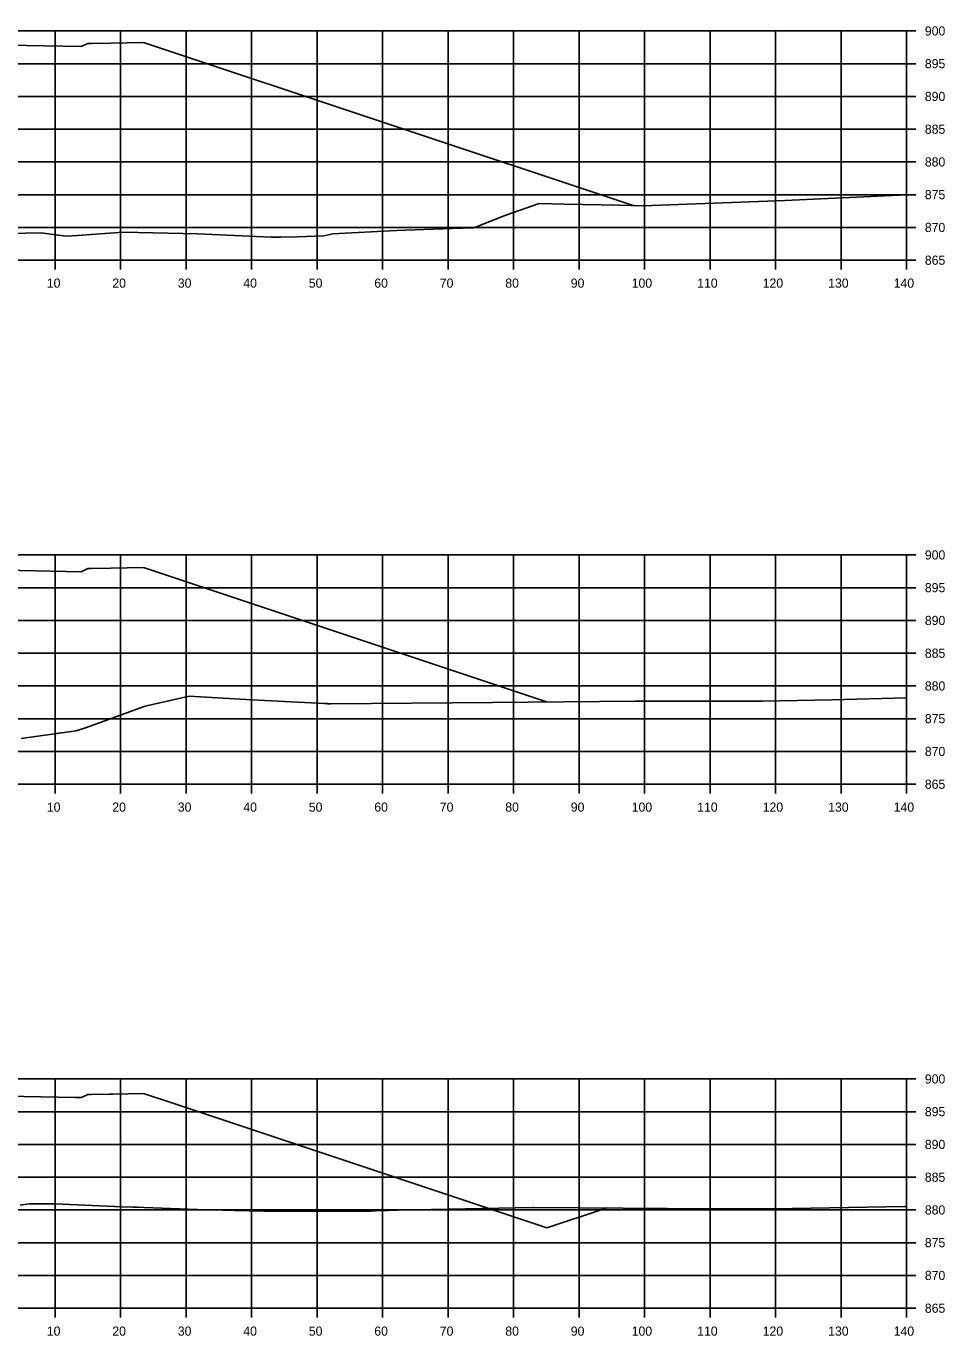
# Model space of a CAD drawing. Extents: x 1098669 to 1198896, y 698679 to 704410.
# Drawn here: x 1113504.5 to 1113644.7, y 702234.3 to 702434.3 of the extents above; entities that cross this region are included whole.
import ezdxf

# ---------------------------------------------------------------- set-up
doc = ezdxf.new("R2010")
doc.units = 0
for name, color, linetype in [('R_Alt Surface', 7, 'Continuous'), ('R_Axis', 7, 'Continuous'), ('R_Axis Annot', 7, 'Continuous'), ('R_Fin Surface', 7, 'Continuous'), ('R_Grid', 7, 'Continuous')]:
    doc.layers.add(name, color=color, linetype=linetype)

msp = doc.modelspace()

# ---------------------------------------------------------------- linework, layer by layer
at = {"layer": 'R_Alt Surface'}
for points in [[(1113497.26, 702402.53), (1113506.69, 702402.73), (1113510.18, 702402.26), (1113510.55, 702402.21), (1113512.3, 702402.34), (1113519.29, 702402.86), (1113530.68, 702402.6), (1113541.84, 702402.08), (1113543.32, 702402.09), (1113545.85, 702402.15), (1113549.89, 702402.27), (1113551.29, 702402.56), (1113561.02, 702403.07), (1113569.51, 702403.4), (1113572.81, 702403.52), (1113577.68, 702405.41), (1113582.79, 702407.2), (1113586.67, 702407.12), (1113595.04, 702406.94), (1113598.59, 702406.87), (1113620.33, 702407.68), (1113638.87, 702408.53)], [(1113503.69, 702325.53), (1113511.32, 702326.6), (1113512.08, 702326.7), (1113513.53, 702327.18), (1113522.61, 702330.47), (1113529.34, 702331.98), (1113537.15, 702331.52), (1113540.91, 702331.34), (1113549.98, 702330.87), (1113550.42, 702330.86), (1113550.45, 702330.85), (1113550.57, 702330.85), (1113550.98, 702330.85), (1113575.64, 702331.02), (1113597.43, 702331.26), (1113613.54, 702331.23), (1113616.89, 702331.21), (1113627.51, 702331.46), (1113638.87, 702331.76)], [(1113503.54, 702254.29), (1113504.92, 702254.48), (1113508.87, 702254.47), (1113519.04, 702254.05), (1113520.73, 702253.99), (1113521.43, 702253.96), (1113522.46, 702253.92), (1113530.58, 702253.61), (1113536.29, 702253.48), (1113540.7, 702253.36), (1113542.91, 702253.39), (1113557.08, 702253.38), (1113558.73, 702253.46), (1113559.71, 702253.46), (1113561.16, 702253.54), (1113581.75, 702253.92), (1113581.84, 702253.92), (1113581.91, 702253.92), (1113581.92, 702253.92), (1113581.99, 702253.92), (1113602.35, 702253.8), (1113611.61, 702253.75), (1113618.61, 702253.73), (1113638.57, 702254.1), (1113638.87, 702254.1)]]:
    msp.add_lwpolyline(points, dxfattribs=at)
at = {"layer": 'R_Axis'}
for p, q in [((1113638.87, 702398.56), (1113638.87, 702433.56)), ((1113640.27, 702433.56), (1113638.87, 702433.56)), ((1113640.27, 702428.56), (1113638.87, 702428.56)), ((1113640.27, 702423.56), (1113638.87, 702423.56)), ((1113640.27, 702418.56), (1113638.87, 702418.56)), ((1113640.27, 702413.56), (1113638.87, 702413.56)), ((1113640.27, 702408.56), (1113638.87, 702408.56)), ((1113640.27, 702403.56), (1113638.87, 702403.56)), ((1113358.87, 702398.56), (1113638.87, 702398.56)), ((1113508.87, 702397.16), (1113508.87, 702398.56)), ((1113518.87, 702397.16), (1113518.87, 702398.56)), ((1113528.87, 702397.16), (1113528.87, 702398.56)), ((1113538.87, 702397.16), (1113538.87, 702398.56)), ((1113548.87, 702397.16), (1113548.87, 702398.56)), ((1113558.87, 702397.16), (1113558.87, 702398.56)), ((1113568.87, 702397.16), (1113568.87, 702398.56)), ((1113578.87, 702397.16), (1113578.87, 702398.56)), ((1113588.87, 702397.16), (1113588.87, 702398.56)), ((1113598.87, 702397.16), (1113598.87, 702398.56)), ((1113608.87, 702397.16), (1113608.87, 702398.56)), ((1113618.87, 702397.16), (1113618.87, 702398.56)), ((1113628.87, 702397.16), (1113628.87, 702398.56)), ((1113638.87, 702397.16), (1113638.87, 702398.56)), ((1113640.27, 702398.56), (1113638.87, 702398.56)), ((1113638.87, 702318.56), (1113638.87, 702353.56)), ((1113640.27, 702353.56), (1113638.87, 702353.56)), ((1113640.27, 702348.56), (1113638.87, 702348.56)), ((1113640.27, 702343.56), (1113638.87, 702343.56)), ((1113640.27, 702338.56), (1113638.87, 702338.56)), ((1113640.27, 702333.56), (1113638.87, 702333.56)), ((1113640.27, 702328.56), (1113638.87, 702328.56)), ((1113640.27, 702323.56), (1113638.87, 702323.56)), ((1113358.87, 702318.56), (1113638.87, 702318.56)), ((1113508.87, 702317.16), (1113508.87, 702318.56)), ((1113518.87, 702317.16), (1113518.87, 702318.56)), ((1113528.87, 702317.16), (1113528.87, 702318.56)), ((1113538.87, 702317.16), (1113538.87, 702318.56)), ((1113548.87, 702317.16), (1113548.87, 702318.56)), ((1113558.87, 702317.16), (1113558.87, 702318.56)), ((1113568.87, 702317.16), (1113568.87, 702318.56)), ((1113578.87, 702317.16), (1113578.87, 702318.56)), ((1113588.87, 702317.16), (1113588.87, 702318.56)), ((1113598.87, 702317.16), (1113598.87, 702318.56)), ((1113608.87, 702317.16), (1113608.87, 702318.56)), ((1113618.87, 702317.16), (1113618.87, 702318.56)), ((1113628.87, 702317.16), (1113628.87, 702318.56)), ((1113638.87, 702317.16), (1113638.87, 702318.56)), ((1113640.27, 702318.56), (1113638.87, 702318.56)), ((1113638.87, 702238.56), (1113638.87, 702273.56)), ((1113640.27, 702273.56), (1113638.87, 702273.56)), ((1113640.27, 702268.56), (1113638.87, 702268.56)), ((1113640.27, 702263.56), (1113638.87, 702263.56)), ((1113640.27, 702258.56), (1113638.87, 702258.56)), ((1113640.27, 702253.56), (1113638.87, 702253.56)), ((1113640.27, 702248.56), (1113638.87, 702248.56)), ((1113640.27, 702243.56), (1113638.87, 702243.56)), ((1113358.87, 702238.56), (1113638.87, 702238.56)), ((1113508.87, 702237.16), (1113508.87, 702238.56)), ((1113518.87, 702237.16), (1113518.87, 702238.56)), ((1113528.87, 702237.16), (1113528.87, 702238.56)), ((1113538.87, 702237.16), (1113538.87, 702238.56)), ((1113548.87, 702237.16), (1113548.87, 702238.56)), ((1113558.87, 702237.16), (1113558.87, 702238.56)), ((1113568.87, 702237.16), (1113568.87, 702238.56)), ((1113578.87, 702237.16), (1113578.87, 702238.56)), ((1113588.87, 702237.16), (1113588.87, 702238.56)), ((1113598.87, 702237.16), (1113598.87, 702238.56)), ((1113608.87, 702237.16), (1113608.87, 702238.56)), ((1113618.87, 702237.16), (1113618.87, 702238.56)), ((1113628.87, 702237.16), (1113628.87, 702238.56)), ((1113638.87, 702237.16), (1113638.87, 702238.56)), ((1113640.27, 702238.56), (1113638.87, 702238.56))]:
    msp.add_line(p, q, dxfattribs=at)
at = {"layer": 'R_Fin Surface'}
for points in [[(1113444.85, 702421.64), (1113454.54, 702424.87), (1113458.59, 702426.22), (1113462.54, 702427.54), (1113475.37, 702431.81), (1113480.37, 702431.71), (1113483.37, 702431.65), (1113483.87, 702431.65), (1113484.87, 702431.17), (1113498.87, 702431.45), (1113512.87, 702431.17), (1113513.87, 702431.65), (1113514.37, 702431.65), (1113517.37, 702431.71), (1113522.37, 702431.81), (1113597.11, 702406.9)], [(1113408.45, 702329.33), (1113427.7, 702335.74), (1113432.99, 702337.5), (1113445.37, 702341.63), (1113455.37, 702344.96), (1113461.27, 702346.93), (1113475.37, 702351.63), (1113480.37, 702351.53), (1113483.37, 702351.47), (1113483.87, 702351.47), (1113484.87, 702350.99), (1113498.87, 702351.27), (1113512.87, 702350.99), (1113513.87, 702351.47), (1113514.37, 702351.47), (1113517.37, 702351.53), (1113522.37, 702351.63), (1113583.92, 702331.11)], [(1113498.87, 702270.99), (1113511.94, 702270.73), (1113512.87, 702270.71), (1113512.93, 702270.74), (1113513.87, 702271.19), (1113513.9, 702271.19), (1113514.37, 702271.19), (1113517.17, 702271.25), (1113517.37, 702271.25), (1113517.7, 702271.26), (1113522.37, 702271.35), (1113526.41, 702270), (1113583.97, 702250.82), (1113592.42, 702253.63), (1113593.09, 702253.86)]]:
    msp.add_lwpolyline(points, dxfattribs=at)
at = {"layer": 'R_Grid'}
for p, q in [((1113358.87, 702433.56), (1113638.87, 702433.56)), ((1113508.87, 702398.56), (1113508.87, 702433.56)), ((1113518.87, 702398.56), (1113518.87, 702433.56)), ((1113528.87, 702398.56), (1113528.87, 702433.56)), ((1113538.87, 702398.56), (1113538.87, 702433.56)), ((1113548.87, 702398.56), (1113548.87, 702433.56)), ((1113558.87, 702398.56), (1113558.87, 702433.56)), ((1113568.87, 702398.56), (1113568.87, 702433.56)), ((1113578.87, 702398.56), (1113578.87, 702433.56)), ((1113588.87, 702398.56), (1113588.87, 702433.56)), ((1113598.87, 702398.56), (1113598.87, 702433.56)), ((1113608.87, 702398.56), (1113608.87, 702433.56)), ((1113618.87, 702398.56), (1113618.87, 702433.56)), ((1113628.87, 702398.56), (1113628.87, 702433.56)), ((1113638.87, 702398.56), (1113638.87, 702433.56)), ((1113358.87, 702428.56), (1113638.87, 702428.56)), ((1113358.87, 702423.56), (1113638.87, 702423.56)), ((1113358.87, 702418.56), (1113638.87, 702418.56)), ((1113358.87, 702413.56), (1113638.87, 702413.56)), ((1113358.87, 702408.56), (1113638.87, 702408.56)), ((1113358.87, 702403.56), (1113638.87, 702403.56)), ((1113358.87, 702398.56), (1113638.87, 702398.56)), ((1113358.87, 702353.56), (1113638.87, 702353.56)), ((1113508.87, 702318.56), (1113508.87, 702353.56)), ((1113518.87, 702318.56), (1113518.87, 702353.56)), ((1113528.87, 702318.56), (1113528.87, 702353.56)), ((1113538.87, 702318.56), (1113538.87, 702353.56)), ((1113548.87, 702318.56), (1113548.87, 702353.56)), ((1113558.87, 702318.56), (1113558.87, 702353.56)), ((1113568.87, 702318.56), (1113568.87, 702353.56)), ((1113578.87, 702318.56), (1113578.87, 702353.56)), ((1113588.87, 702318.56), (1113588.87, 702353.56)), ((1113598.87, 702318.56), (1113598.87, 702353.56)), ((1113608.87, 702318.56), (1113608.87, 702353.56)), ((1113618.87, 702318.56), (1113618.87, 702353.56)), ((1113628.87, 702318.56), (1113628.87, 702353.56)), ((1113638.87, 702318.56), (1113638.87, 702353.56)), ((1113358.87, 702348.56), (1113638.87, 702348.56)), ((1113358.87, 702343.56), (1113638.87, 702343.56)), ((1113358.87, 702338.56), (1113638.87, 702338.56)), ((1113358.87, 702333.56), (1113638.87, 702333.56)), ((1113358.87, 702328.56), (1113638.87, 702328.56)), ((1113358.87, 702323.56), (1113638.87, 702323.56)), ((1113358.87, 702318.56), (1113638.87, 702318.56)), ((1113358.87, 702273.56), (1113638.87, 702273.56)), ((1113508.87, 702238.56), (1113508.87, 702273.56)), ((1113518.87, 702238.56), (1113518.87, 702273.56)), ((1113528.87, 702238.56), (1113528.87, 702273.56)), ((1113538.87, 702238.56), (1113538.87, 702273.56)), ((1113548.87, 702238.56), (1113548.87, 702273.56)), ((1113558.87, 702238.56), (1113558.87, 702273.56)), ((1113568.87, 702238.56), (1113568.87, 702273.56)), ((1113578.87, 702238.56), (1113578.87, 702273.56)), ((1113588.87, 702238.56), (1113588.87, 702273.56)), ((1113598.87, 702238.56), (1113598.87, 702273.56)), ((1113608.87, 702238.56), (1113608.87, 702273.56)), ((1113618.87, 702238.56), (1113618.87, 702273.56)), ((1113628.87, 702238.56), (1113628.87, 702273.56)), ((1113638.87, 702238.56), (1113638.87, 702273.56)), ((1113358.87, 702268.56), (1113638.87, 702268.56)), ((1113358.87, 702263.56), (1113638.87, 702263.56)), ((1113358.87, 702258.56), (1113638.87, 702258.56)), ((1113358.87, 702253.56), (1113638.87, 702253.56)), ((1113358.87, 702248.56), (1113638.87, 702248.56)), ((1113358.87, 702243.56), (1113638.87, 702243.56)), ((1113358.87, 702238.56), (1113638.87, 702238.56))]:
    msp.add_line(p, q, dxfattribs=at)

# ---------------------------------------------------------------- texts
at = {"layer": 'R_Axis Annot'}
for s, p in [('900', (1113641.67, 702432.86)), ('895', (1113641.67, 702427.86)), ('890', (1113641.67, 702422.86)), ('885', (1113641.67, 702417.86)), ('880', (1113641.67, 702412.86)), ('875', (1113641.67, 702407.86)), ('870', (1113641.67, 702402.86)), ('865', (1113641.67, 702397.86)), ('10', (1113507.61, 702394.36)), ('20', (1113517.61, 702394.36)), ('30', (1113527.61, 702394.36)), ('40', (1113537.61, 702394.36)), ('50', (1113547.61, 702394.36)), ('60', (1113557.61, 702394.36)), ('70', (1113567.61, 702394.36)), ('80', (1113577.61, 702394.36)), ('90', (1113587.61, 702394.36)), ('100', (1113596.91, 702394.36)), ('110', (1113606.91, 702394.36)), ('120', (1113616.91, 702394.36)), ('130', (1113626.91, 702394.36)), ('140', (1113636.91, 702394.36)), ('900', (1113641.67, 702352.86)), ('895', (1113641.67, 702347.86)), ('890', (1113641.67, 702342.86)), ('885', (1113641.67, 702337.86)), ('880', (1113641.67, 702332.86)), ('875', (1113641.67, 702327.86)), ('870', (1113641.67, 702322.86)), ('865', (1113641.67, 702317.86)), ('10', (1113507.61, 702314.36)), ('20', (1113517.61, 702314.36)), ('30', (1113527.61, 702314.36)), ('40', (1113537.61, 702314.36)), ('50', (1113547.61, 702314.36)), ('60', (1113557.61, 702314.36)), ('70', (1113567.61, 702314.36)), ('80', (1113577.61, 702314.36)), ('90', (1113587.61, 702314.36)), ('100', (1113596.91, 702314.36)), ('110', (1113606.91, 702314.36)), ('120', (1113616.91, 702314.36)), ('130', (1113626.91, 702314.36)), ('140', (1113636.91, 702314.36)), ('900', (1113641.67, 702272.86)), ('895', (1113641.67, 702267.86)), ('890', (1113641.67, 702262.86)), ('885', (1113641.67, 702257.86)), ('880', (1113641.67, 702252.86)), ('875', (1113641.67, 702247.86)), ('870', (1113641.67, 702242.86)), ('865', (1113641.67, 702237.86)), ('10', (1113507.61, 702234.36)), ('20', (1113517.61, 702234.36)), ('30', (1113527.61, 702234.36)), ('40', (1113537.61, 702234.36)), ('50', (1113547.61, 702234.36)), ('60', (1113557.61, 702234.36)), ('70', (1113567.61, 702234.36)), ('80', (1113577.61, 702234.36)), ('90', (1113587.61, 702234.36)), ('100', (1113596.91, 702234.36)), ('110', (1113606.91, 702234.36)), ('120', (1113616.91, 702234.36)), ('130', (1113626.91, 702234.36)), ('140', (1113636.91, 702234.36))]:
    msp.add_text(s, height=1.4, dxfattribs=at).set_placement(p)

doc.saveas('drawing.dxf')
